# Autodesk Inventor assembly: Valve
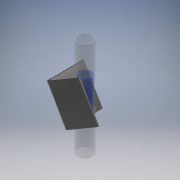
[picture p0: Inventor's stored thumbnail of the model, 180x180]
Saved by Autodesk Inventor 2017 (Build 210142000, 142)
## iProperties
Created: 2020-03
Part Number: Valve
Description: STEP AP203
Document SubType Name: Assembly
Designer: user
Sending System: SolidWorks 2018
Preprocessor: SwSTEP 2.0
Title: Assem1.STEP
Revision Number: ANY
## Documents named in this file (7)
- C:\Users\user\Downloads\Valve.iam
- C:\Users\user\Downloads\ball.ipt
- C:\Users\user\Downloads\bracket.ipt
- C:\Users\user\Downloads\rubber seal.ipt
- C:\Users\user\Downloads\Syringe.ipt
- C:\Users\user\Downloads\Tube.ipt
- C:\Users\user\Downloads\interrupt.ipt
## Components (7 placed, 7 different names)
1. ball_1
2. bracket_2
3. rubber seal_3
4. Syringe_4
5. Tube_5
6. Tube_6
7. interrupt_7
